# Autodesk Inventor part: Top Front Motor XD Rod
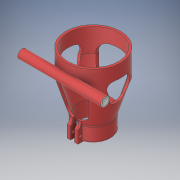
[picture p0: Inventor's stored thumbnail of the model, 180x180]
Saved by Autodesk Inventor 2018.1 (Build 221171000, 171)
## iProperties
Created: 2018-06
Part Number: Top Front Motor XD Rod
Material: Generic
Document SubType Name: Modeling
Designer: Ryan
Density: 1 g/cm^3
Appearance: Default
Author: Ryan
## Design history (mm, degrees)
derived "Assembly3 Part out.iam"
sketch "Sketch1"
  geometry: L1 (-38.527, 77.015)-(136.232, 77.015); L2 (136.232, 77.015)-(136.232, -217.058); L3 (136.232, -217.058)-(-38.527, -217.058); L4 (-38.527, -217.058)-(-38.527, 77.015); 1 further point
  constraints: 8 end point, 2 parallel, 1 horizontal, 1 perpendicular
extrude "Extrusion1" cut sketch "Sketch1" distance "d1" = 25.4; taper "d2" = 0 deg
workplane "Work Plane2"
  workplane "Work Plane1"
workpoint "Work Point1"
workplane "Work Plane3"
workplane "Work Plane4"
workplane "Work Plane5"
workplane "Work Plane6"
workplane "Work Plane7"
workplane "Work Plane8"
workplane "Work Plane9"
workplane "Work Plane10"
workplane "Work Plane11"
workplane "Work Plane12"
sketch "Sketch2"
  geometry: L1 (227.789, 28.997)-(-104.46, 28.997); L2 (-104.46, 28.997)-(-104.46, -117.244); L3 (-104.46, -117.244)-(227.789, -117.244); L4 (227.789, -117.244)-(227.789, 28.997); 1 further point
  constraints: 8 end point, 2 parallel, 1 horizontal, 1 perpendicular
extrude "Extrusion2" cut sketch "Sketch2" distance "d10" = 169.8625; taper "d11" = 0 deg
sketch "Sketch3"
  geometry: L1 (244.466, 43.749)-(-96.122, 43.749); L2 (-96.122, 43.749)-(-96.122, -113.396); L3 (-96.122, -113.396)-(244.466, -113.396); L4 (244.466, -113.396)-(244.466, 43.749); 1 further point
  constraints: 8 end point, 2 parallel, 1 horizontal, 1 perpendicular
extrude "Extrusion3" cut sketch "Sketch3" distance "d12" = 169.8625; taper "d13" = 0 deg
sketch "Sketch4"
  geometry: L1 (228.431, 30.28)-(156.593, 30.28); L2 (156.593, 30.28)-(156.593, -87.098); L3 (156.593, -87.098)-(228.431, -87.098); L4 (228.431, -87.098)-(228.431, 30.28); L5 (-98.688, 23.865)-(-20.436, 23.865); L6 (-20.436, 23.865)-(-20.436, -58.235); L7 (-20.436, -58.235)-(-98.688, -58.235); L8 (-98.688, -58.235)-(-98.688, 23.865); 1 further point
  constraints: 16 end point, 4 parallel, 2 horizontal, 2 perpendicular
extrude "Extrusion4" cut sketch "Sketch4" distance "d14" = 169.8625; taper "d15" = 0 deg
sketch "Sketch5"
  geometry: L1 (-117.93, 39.259)-(22.538, 39.259); L2 (22.538, 39.259)-(22.538, -121.093); L3 (22.538, -121.093)-(-117.93, -121.093); L4 (-117.93, -121.093)-(-117.93, 39.259); 1 further point
  constraints: 8 end point, 2 parallel, 1 horizontal, 1 perpendicular
extrude "Extrusion5" cut sketch "Sketch5" distance "d16" = 174.625; taper "d17" = 0 deg
sketch "Sketch6"
  geometry: C1 r 4.763 at (0, 0) reference; C2 r 3.429 at (0, 0); 1 further point
  constraints: 1 centre point, 1 coincident
  dimensions: "d19" = 6.858 diameter of C2
sketch "Sketch7"
  geometry: C1 r 4.763 at (0, 0) reference; C2 r 3.429 at (0, 0); 1 further point
  constraints: 1 centre point, 1 coincident
  dimensions: "d20" = 6.858 diameter of C2
extrude "Extrusion6" cut sketch "Sketch7" distance "d21" = 12.7; taper "d22" = 0 deg
extrude "Extrusion7" cut sketch "Sketch6" distance "d23" = 12.7; taper "d24" = 0 deg
body "Solid1"
node "Rov v4.2.ipt:1" dims "d0" = 10
node "Motor mount.ipt:1" dims "d0" = 10
node "Motor mount.ipt:2" dims "d0" = 10
node "Motor mount_MIR2.ipt:1" dims "d0" = 10
other parameters: "d3" = 6.35, "d4" = 12.7, "d5" = -12.7, "d6" = 12.7, "d7" = -12.7, "d8" = 6.35, "d9" = -6.35
